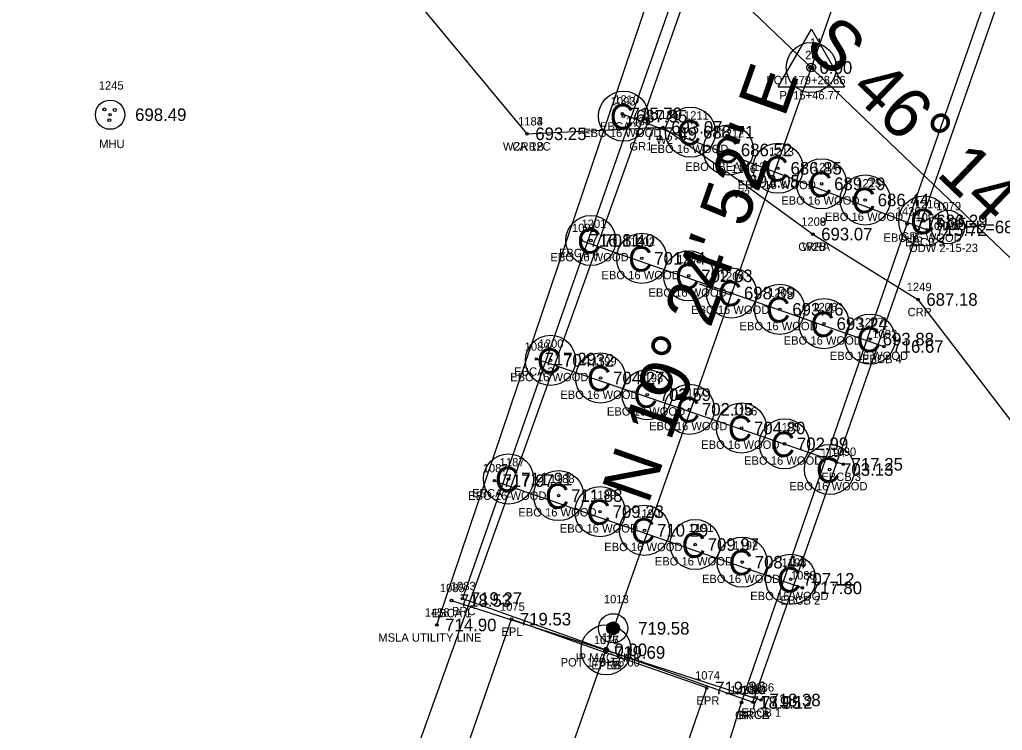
# Model space of a CAD drawing. Extents: x 1736563 to 1738032, y 1150548 to 1154248.
# Drawn here: x 1737322 to 1737439.5, y 1152598.1 to 1152683.1 of the extents above; entities that cross this region are included whole.
import ezdxf

# ---------------------------------------------------------------- set-up
doc = ezdxf.new("R2010")
doc.units = 0
for name, color, linetype in [('RD_EX_BldgApp', 7, 'Continuous'), ('RD_EX_Bridge', 7, 'Continuous'), ('RD_EX_Bridge_txCode', 7, 'Continuous'), ('RD_EX_DR_Inlet', 7, 'Continuous'), ('RD_EX_DV_Prop_txCode', 7, 'Continuous'), ('RD_EX_DV_PropPin', 7, 'Continuous'), ('RD_EX_GuardRail', 7, 'Continuous'), ('RD_EX_GuardRail_txCode', 7, 'Continuous'), ('RD_EX_H2O', 7, 'Continuous'), ('RD_EX_H2O_txCode', 7, 'Continuous'), ('RD_EX_Misc', 7, 'Continuous'), ('RD_EX_Misc_txCode', 7, 'Continuous'), ('RD_EX_Road', 7, 'Continuous'), ('RD_EX_Road_txCode', 7, 'Continuous'), ('RD_EX_TX_Bridge_ELEV', 7, 'Continuous'), ('RD_EX_TX_DV_Prop_ELEV', 7, 'Continuous'), ('RD_EX_TX_GuardRail_ELEV', 7, 'Continuous'), ('RD_EX_TX_H2O_ELEV', 7, 'Continuous'), ('RD_EX_TX_Misc_ELEV', 7, 'Continuous'), ('RD_EX_TX_Road_ELEV', 7, 'Continuous'), ('RD_EX_TX_UT_ELEV', 7, 'Continuous'), ('RD_EX_UT_txCode', 7, 'Continuous'), ('RD_HC_Cl', 7, 'Continuous'), ('RD_HC_Data', 7, 'Continuous'), ('RD_HC_Data_Tic', 7, 'Continuous'), ('RD_HC_Survey_ELEV', 7, 'Continuous'), ('RD_HC_txCode', 7, 'Continuous'), ('RD_SMD_Locator', 7, 'Continuous')]:
    doc.layers.add(name, color=color, linetype=linetype)

msp = doc.modelspace()

# ---------------------------------------------------------------- linework, layer by layer
at = {"layer": 'RD_EX_BldgApp'}
msp.add_lwpolyline([(1737382.66, 1152669.43), (1737398.93, 1152670.21), (1737408.18, 1152663.75), (1737416.87, 1152657.43)], dxfattribs=at)
at = {"layer": 'RD_EX_Bridge'}
for p, q in [((1737394.07, 1152671.82), (1737430.53, 1152657.96)), ((1737389.15, 1152656.68), (1737425.38, 1152643.99)), ((1737383.78, 1152642.49), (1737420.51, 1152629.9)), ((1737378.75, 1152627.93), (1737415.62, 1152615.11)), ((1737373.63, 1152613.6), (1737410.67, 1152601.69))]:
    msp.add_line(p, q, dxfattribs=at)
msp.add_lwpolyline([(1737409.7, 1152601.42), (1737459.22, 1152742.78), (1737424.43, 1152755.18), (1737374.94, 1152613.83), (1737409.7, 1152601.42)], dxfattribs=at)
for centre in [(1737394.21, 1152671.54), (1737402.23, 1152669.63), (1737406.76, 1152667.5), (1737412.7, 1152665.31), (1737417.92, 1152663.45), (1737423.13, 1152661.51), (1737430.14, 1152659.01), (1737390.3, 1152656.67), (1737396.4, 1152654.53), (1737402.02, 1152652.44), (1737407.13, 1152650.38), (1737412.91, 1152648.43), (1737418.21, 1152646.71), (1737423.73, 1152644.87), (1737385.48, 1152642.33), (1737391.47, 1152640.22), (1737397.05, 1152638.22), (1737402.1, 1152636.47), (1737408.33, 1152634.24), (1737413.47, 1152632.34), (1737418.87, 1152629.27), (1737380.46, 1152628.14), (1737386.45, 1152626.15), (1737391.41, 1152624.23), (1737396.73, 1152622), (1737402.79, 1152620.29), (1737408.42, 1152618.19), (1737414.21, 1152616.14)]:
    msp.add_circle(centre, 3, dxfattribs=at)
at = {"layer": 'RD_EX_DR_Inlet'}
for centre, radius in [((1737332.78, 1152671.72), 1.75), ((1737332.11, 1152672.35), 0.175), ((1737333.34, 1152672.28), 0.175), ((1737332.69, 1152671.06), 0.175)]:
    msp.add_circle(centre, radius, dxfattribs=at)
at = {"layer": 'RD_EX_DV_PropPin'}
for p, q in [((1737392.27, 1152609.97), (1737392.27, 1152610.56)), ((1737392.31, 1152609.9), (1737392.31, 1152610.64)), ((1737392.34, 1152609.84), (1737392.34, 1152610.69)), ((1737392.38, 1152609.79), (1737392.38, 1152610.74)), ((1737392.41, 1152609.75), (1737392.41, 1152610.78)), ((1737392.45, 1152609.72), (1737392.45, 1152610.82)), ((1737392.48, 1152609.68), (1737392.48, 1152610.85)), ((1737392.52, 1152609.66), (1737392.52, 1152610.88)), ((1737392.55, 1152609.63), (1737392.55, 1152610.9)), ((1737392.59, 1152609.61), (1737392.59, 1152610.92)), ((1737392.62, 1152609.59), (1737392.62, 1152610.94)), ((1737392.66, 1152609.57), (1737392.66, 1152610.96)), ((1737392.69, 1152609.56), (1737392.69, 1152610.97)), ((1737392.73, 1152609.55), (1737392.73, 1152610.99)), ((1737392.76, 1152609.54), (1737392.76, 1152611)), ((1737392.8, 1152609.53), (1737392.8, 1152611.01)), ((1737392.83, 1152609.52), (1737392.83, 1152611.02)), ((1737392.87, 1152609.51), (1737392.87, 1152611.02)), ((1737392.9, 1152609.51), (1737392.9, 1152611.02)), ((1737392.94, 1152609.51), (1737392.94, 1152611.03)), ((1737392.97, 1152609.51), (1737392.97, 1152611.03)), ((1737393.01, 1152609.51), (1737393.01, 1152611.03)), ((1737393.04, 1152609.51), (1737393.04, 1152611.02)), ((1737393.08, 1152609.51), (1737393.08, 1152611.02)), ((1737393.11, 1152609.52), (1737393.11, 1152611.02)), ((1737393.15, 1152609.53), (1737393.15, 1152611.01)), ((1737393.18, 1152609.54), (1737393.18, 1152611)), ((1737393.22, 1152609.55), (1737393.22, 1152610.99)), ((1737393.25, 1152609.56), (1737393.25, 1152610.97)), ((1737393.29, 1152609.57), (1737393.29, 1152610.96)), ((1737393.32, 1152609.59), (1737393.32, 1152610.94)), ((1737393.36, 1152609.61), (1737393.36, 1152610.92)), ((1737393.39, 1152609.63), (1737393.39, 1152610.9)), ((1737393.43, 1152609.66), (1737393.43, 1152610.88)), ((1737393.46, 1152609.68), (1737393.46, 1152610.85)), ((1737393.5, 1152609.72), (1737393.5, 1152610.82)), ((1737393.53, 1152609.75), (1737393.53, 1152610.78)), ((1737393.57, 1152609.79), (1737393.57, 1152610.74)), ((1737393.6, 1152609.84), (1737393.6, 1152610.69)), ((1737393.64, 1152609.9), (1737393.64, 1152610.64)), ((1737393.67, 1152609.97), (1737393.67, 1152610.56)), ((1737392.24, 1152610.07), (1737392.24, 1152610.46)), ((1737393.71, 1152610.07), (1737393.71, 1152610.46))]:
    msp.add_line(p, q, dxfattribs=at)
for radius in [1.75, 0.761]:
    msp.add_circle((1737392.97, 1152610.27), radius, dxfattribs=at)
at = {"layer": 'RD_EX_GuardRail'}
for points in [[(1737338.24, 1152511.65), (1737369.14, 1152594.73), (1737395.87, 1152669.44), (1737425.76, 1152754.51), (1737455.78, 1152858.18)], [(1737351.87, 1152429.26), (1737391.13, 1152545.98), (1737408.34, 1152601.39), (1737428.16, 1152658.66), (1737456.13, 1152738.69), (1737462.06, 1152749.07), (1737464.76, 1152758.57), (1737497.67, 1152845.09)]]:
    msp.add_lwpolyline(points, dxfattribs=at)
at = {"layer": 'RD_EX_H2O'}
for points in [[(1736941.84, 1152927.33), (1737042.79, 1152891.61), (1737121.65, 1152865.9), (1737201.8, 1152833.83), (1737271.75, 1152787.96), (1737327.38, 1152737.27), (1737368.53, 1152686.45), (1737382.66, 1152669.43)], [(1737416.87, 1152657.43), (1737429.45, 1152649.61), (1737450.39, 1152622.3), (1737469.7, 1152595.53), (1737481.35, 1152535.91), (1737513.9, 1152523.3), (1737579.93, 1152459.05), (1737654.23, 1152384.64), (1737738.06, 1152318.16), (1737784.96, 1152282.34)]]:
    msp.add_lwpolyline(points, dxfattribs=at)
for radius in [2, 0.15]:
    msp.add_circle((1737433.02, 1152658.28), radius, dxfattribs=at)
at = {"layer": 'RD_EX_Misc'}
msp.add_line((1737371.88, 1152610.67), (1737424.27, 1152765.64), dxfattribs=at)
at = {"layer": 'RD_EX_Road'}
for points in [[(1736868.01, 1151157.6), (1736882.54, 1151196.52), (1736892.4, 1151226.58), (1736911.77, 1151279.81), (1736926.32, 1151321.94), (1736959.92, 1151418.27), (1736977.6, 1151467.57), (1736993.86, 1151514.24), (1737026.63, 1151607.21), (1737059.17, 1151698.64), (1737091.53, 1151790.84), (1737119.9, 1151870.3), (1737125.51, 1151887.21), (1737129.74, 1151897.31), (1737157.61, 1151979.19), (1737191.07, 1152073.18), (1737224.57, 1152167.62), (1737258.08, 1152262.33), (1737292.51, 1152359.5), (1737326.83, 1152457.35), (1737361.84, 1152556.63), (1737380.81, 1152611.37), (1737392.07, 1152607.38)], [(1737114.69, 1151782.27), (1737149.29, 1151879.88), (1737171.36, 1151942.06), (1737180.55, 1151968.4), (1737214.61, 1152064.48), (1737248.04, 1152159.34), (1737281.83, 1152253.71), (1737315.68, 1152350.56), (1737350.18, 1152448.39), (1737384.95, 1152547.7), (1737404.17, 1152603.14), (1737392.07, 1152607.38)]]:
    msp.add_lwpolyline(points, dxfattribs=at)
at = {"layer": 'RD_HC_Cl'}
for p, q in [((1736879.96, 1151154.46), (1737935.1, 1154148.31)), ((1737384.75, 1152707.94), (1737485.65, 1152611.3))]:
    msp.add_line(p, q, dxfattribs=at)
at = {"layer": 'RD_HC_Data'}
for p, q in [((1737412.71, 1152675.06), (1737416.69, 1152681.94)), ((1737416.69, 1152681.94), (1737420.65, 1152675.06)), ((1737412.71, 1152675.06), (1737420.65, 1152675.06))]:
    msp.add_line(p, q, dxfattribs=at)
for centre, radius in [((1737416.68, 1152677.36), 3), ((1737416.68, 1152677.36), 0.529), ((1737416.68, 1152677.36), 0.282), ((1737392.13, 1152607.7), 3), ((1737392.13, 1152607.7), 0.282)]:
    msp.add_circle(centre, radius, dxfattribs=at)
at = {"layer": 'RD_HC_Data_Tic'}
msp.add_line((1737407.09, 1152650.13), (1737403.32, 1152651.46), dxfattribs=at)
at = {"layer": 'RD_SMD_Locator'}
for centre in [(1737416.68, 1152677.36), (1737416.68, 1152677.36), (1737332.78, 1152671.72), (1737394.07, 1152671.82), (1737394.21, 1152671.54), (1737382.66, 1152669.43), (1737382.66, 1152669.43), (1737395.87, 1152669.44), (1737398.93, 1152670.21), (1737402.23, 1152669.63), (1737406.76, 1152667.5), (1737412.7, 1152665.31), (1737408.18, 1152663.75), (1737417.92, 1152663.45), (1737423.13, 1152661.51), (1737428.16, 1152658.66), (1737430.14, 1152659.01), (1737430.53, 1152657.96), (1737389.15, 1152656.68), (1737390.3, 1152656.67), (1737416.87, 1152657.43), (1737416.87, 1152657.43), (1737396.4, 1152654.53), (1737402.02, 1152652.44), (1737407.13, 1152650.38), (1737429.45, 1152649.61), (1737412.91, 1152648.43), (1737418.21, 1152646.71), (1737423.73, 1152644.87), (1737425.38, 1152643.99), (1737383.78, 1152642.49), (1737385.48, 1152642.33), (1737391.47, 1152640.22), (1737397.05, 1152638.22), (1737402.1, 1152636.47), (1737408.33, 1152634.24), (1737413.47, 1152632.34), (1737418.87, 1152629.27), (1737420.51, 1152629.9), (1737380.46, 1152628.14), (1737378.75, 1152627.93), (1737386.45, 1152626.15), (1737391.41, 1152624.23), (1737396.73, 1152622), (1737402.79, 1152620.29), (1737408.42, 1152618.19), (1737414.21, 1152616.14), (1737415.62, 1152615.11), (1737373.63, 1152613.6), (1737374.94, 1152613.83), (1737371.88, 1152610.67), (1737380.81, 1152611.37), (1737392.97, 1152610.27), (1737392.07, 1152607.38), (1737392.07, 1152607.38), (1737392.13, 1152607.7), (1737404.17, 1152603.14), (1737408.34, 1152601.39), (1737409.7, 1152601.42), (1737409.7, 1152601.42), (1737410.67, 1152601.69)]:
    msp.add_circle(centre, 0.15, dxfattribs=at)

# ---------------------------------------------------------------- texts
at = {"layer": 'RD_EX_Bridge'}
for p in [(1737392.58, 1152669.98), (1737400.6, 1152668.07), (1737405.13, 1152665.94), (1737411.07, 1152663.74), (1737416.29, 1152661.89), (1737421.5, 1152659.95), (1737428.51, 1152657.45), (1737388.67, 1152655.11), (1737394.77, 1152652.96), (1737400.39, 1152650.88), (1737405.49, 1152648.82), (1737411.28, 1152646.87), (1737416.58, 1152645.14), (1737422.1, 1152643.31), (1737383.85, 1152640.77), (1737389.84, 1152638.65), (1737395.42, 1152636.66), (1737400.47, 1152634.91), (1737406.7, 1152632.67), (1737411.84, 1152630.78), (1737417.24, 1152627.71), (1737378.83, 1152626.58), (1737384.82, 1152624.59), (1737389.78, 1152622.67), (1737395.1, 1152620.44), (1737401.16, 1152618.73), (1737406.79, 1152616.63), (1737412.58, 1152614.57)]:
    msp.add_text('C', height=3, dxfattribs=at).set_placement(p)
at = {"layer": 'RD_EX_Bridge_txCode'}
for s, p in [('1210', (1737393.11, 1152673.04)), ('1093', (1737392.68, 1152672.82)), ('1211', (1737401.45, 1152671.13)), ('EBCA 5', (1737391.41, 1152669.82)), ('EBO 16 WOOD', (1737389.38, 1152669.04)), ('1212', (1737405.7, 1152669)), ('EBO 16 WOOD', (1737397.4, 1152667.13)), ('1213', (1737411.63, 1152666.81)), ('EBO I BEAM 12', (1737401.61, 1152665)), ('1214', (1737416.86, 1152664.95)), ('EBO 16 WOOD', (1737407.87, 1152662.81)), ('1215', (1737422.07, 1152663.01)), ('EBO 16 WOOD', (1737413.09, 1152660.95)), ('1216', (1737429.06, 1152660.51)), ('EBO 16 WOOD', (1737418.31, 1152659.01)), ('1094', (1737429.14, 1152658.96)), ('1201', (1737389.19, 1152658.17)), ('1091', (1737388.05, 1152657.68)), ('1202', (1737395.02, 1152656.03)), ('EBO 16 WOOD', (1737425.32, 1152656.51)), ('EBCB 5', (1737427.9, 1152655.96)), ('EBCA 4', (1737386.49, 1152654.68)), ('EBO 16 WOOD', (1737385.47, 1152654.17)), ('1203', (1737400.64, 1152653.94)), ('EBO 16 WOOD', (1737391.58, 1152652.03)), ('1204', (1737405.74, 1152651.88)), ('EBO 16 WOOD', (1737397.2, 1152649.94)), ('1205', (1737411.53, 1152649.93)), ('EBO 16 WOOD', (1737402.3, 1152647.88)), ('1206', (1737416.8, 1152648.21)), ('1207', (1737422.34, 1152646.37)), ('EBO 16 WOOD', (1737408.09, 1152645.93)), ('1092', (1737423.99, 1152644.99)), ('1200', (1737384.06, 1152643.83)), ('EBO 16 WOOD', (1737413.38, 1152644.21)), ('1089', (1737382.39, 1152643.49)), ('1199', (1737390.41, 1152641.72)), ('EBO 16 WOOD', (1737418.9, 1152642.37)), ('EBCB 4', (1737422.76, 1152641.99)), ('EBCA 3', (1737381.13, 1152640.49)), ('EBO 16 WOOD', (1737380.66, 1152639.83)), ('1198', (1737395.99, 1152639.72)), ('1197', (1737401.04, 1152637.97)), ('EBO 16 WOOD', (1737386.65, 1152637.72)), ('EBO 16 WOOD', (1737392.23, 1152635.72)), ('1196', (1737407.25, 1152635.74)), ('EBO 16 WOOD', (1737397.28, 1152633.97)), ('1195', (1737412.4, 1152633.84)), ('EBO 16 WOOD', (1737403.51, 1152631.74)), ('1194', (1737417.81, 1152630.77)), ('1090', (1737419.08, 1152630.9)), ('1187', (1737379.4, 1152629.64)), ('EBO 16 WOOD', (1737408.64, 1152629.84)), ('1087', (1737377.37, 1152628.93)), ('1188', (1737385.39, 1152627.65)), ('EBCB 3', (1737417.88, 1152627.9)), ('EBO 16 WOOD', (1737414.05, 1152626.77)), ('EBO 16 WOOD', (1737375.63, 1152625.64)), ('EBCA 2', (1737376.1, 1152625.93)), ('1189', (1737390.35, 1152625.73)), ('EBO 16 WOOD', (1737381.63, 1152623.65)), ('1190', (1737395.63, 1152623.5)), ('EBO 16 WOOD', (1737386.59, 1152621.73)), ('1191', (1737402.01, 1152621.79)), ('EBO 16 WOOD', (1737391.91, 1152619.5)), ('1192', (1737407.36, 1152619.69)), ('EBO 16 WOOD', (1737397.96, 1152617.79)), ('1193', (1737413.14, 1152617.64)), ('EBO 16 WOOD', (1737403.6, 1152615.69)), ('1088', (1737414.24, 1152616.11)), ('1085', (1737372.24, 1152614.6)), ('1083', (1737373.56, 1152614.83)), ('EBO 16 WOOD', (1737409.38, 1152613.64)), ('EBCB 2', (1737413, 1152613.11)), ('EBCA 1', (1737371.26, 1152611.6)), ('BRC', (1737373.69, 1152611.83)), ('1086', (1737409.26, 1152602.69)), ('1080', (1737408.28, 1152602.42)), ('1084', (1737408.32, 1152602.42)), ('BRCA', (1737407.96, 1152599.42)), ('BRCB', (1737407.98, 1152599.42)), ('EBCB 1', (1737408.33, 1152599.69))]:
    msp.add_text(s, height=1, dxfattribs=at).set_placement(p)
at = {"layer": 'RD_EX_DV_Prop_txCode'}
for s, p in [('1013', (1737391.87, 1152613.27)), ('IP MAG NAIL', (1737388.48, 1152606.27))]:
    msp.add_text(s, height=1, dxfattribs=at).set_placement(p)
at = {"layer": 'RD_EX_GuardRail_txCode'}
for s, p in [('1439', (1737394.52, 1152670.44)), ('GR1', (1737394.92, 1152667.44)), ('1436', (1737426.79, 1152659.66)), ('GR', (1737427.38, 1152656.66)), ('1435', (1737407, 1152602.39)), ('GR', (1737407.56, 1152599.39))]:
    msp.add_text(s, height=1, dxfattribs=at).set_placement(p)
at = {"layer": 'RD_EX_H2O'}
msp.add_text('ODW', height=1, dxfattribs=at).set_placement((1737431.35, 1152657.9))
at = {"layer": 'RD_EX_H2O_txCode'}
for s, p in [('1184', (1737381.6, 1152670.43)), ('CRRB', (1737380.93, 1152667.43)), ('1079', (1737431.63, 1152660.28)), ('1209', (1737415.48, 1152658.43)), ('CRRA', (1737415.13, 1152655.43)), ('ODW 2-15-23', (1737428.37, 1152655.28)), ('1249', (1737428.1, 1152650.61)), ('CRR', (1737428.2, 1152647.61))]:
    msp.add_text(s, height=1, dxfattribs=at).set_placement(p)
at = {"layer": 'RD_EX_Misc_txCode'}
for s, p in [('1185', (1737397.87, 1152671.21)), ('1183', (1737381.6, 1152670.43)), ('W2A 12C', (1737379.78, 1152667.43)), ('W2', (1737398.11, 1152668.21)), ('1186', (1737407.1, 1152664.75)), ('W2', (1737407.36, 1152661.75)), ('1208', (1737415.48, 1152658.43)), ('W2B', (1737415.58, 1152655.43)), ('1458', (1737370.44, 1152611.67)), ('MSLA UTILITY LINE', (1737364.88, 1152608.67))]:
    msp.add_text(s, height=1, dxfattribs=at).set_placement(p)
at = {"layer": 'RD_EX_Road_txCode'}
for s, p in [('1075', (1737379.43, 1152612.37)), ('EPL', (1737379.61, 1152609.37)), ('1076', (1737390.66, 1152608.38)), ('1077', (1737390.68, 1152608.38)), ('EPRB', (1737390.37, 1152605.38)), ('EPLB', (1737390.39, 1152605.38)), ('1074', (1737402.78, 1152604.14)), ('EPR', (1737402.94, 1152601.14))]:
    msp.add_text(s, height=1, dxfattribs=at).set_placement(p)
at = {"layer": 'RD_EX_TX_Bridge_ELEV'}
for s, p in [('715.70', (1737395.07, 1152671.07)), ('687.95', (1737395.71, 1152670.79)), ('688.71', (1737403.73, 1152668.88)), ('686.52', (1737408.26, 1152666.75)), ('686.85', (1737414.2, 1152664.56)), ('689.29', (1737419.42, 1152662.7)), ('686.44', (1737424.63, 1152660.76)), ('686.29', (1737431.64, 1152658.26)), ('715.72', (1737431.53, 1152657.21)), ('716.81', (1737390.15, 1152655.93)), ('701.40', (1737391.8, 1152655.92)), ('701.24', (1737397.9, 1152653.78)), ('702.63', (1737403.52, 1152651.69)), ('698.89', (1737408.63, 1152649.63)), ('693.46', (1737414.41, 1152647.68)), ('693.24', (1737419.71, 1152645.96)), ('693.88', (1737425.23, 1152644.12)), ('716.67', (1737426.38, 1152643.24)), ('717.29', (1737384.78, 1152641.74)), ('704.32', (1737386.98, 1152641.58)), ('704.27', (1737392.97, 1152639.47)), ('703.59', (1737398.55, 1152637.47)), ('702.05', (1737403.6, 1152635.72)), ('704.80', (1737409.83, 1152633.49)), ('702.99', (1737414.97, 1152631.59)), ('717.25', (1737421.51, 1152629.15)), ('703.13', (1737420.37, 1152628.52)), ('717.97', (1737379.75, 1152627.18)), ('711.91', (1737381.96, 1152627.39)), ('711.88', (1737387.95, 1152625.4)), ('709.23', (1737392.91, 1152623.48)), ('710.29', (1737398.23, 1152621.25)), ('709.97', (1737404.29, 1152619.54)), ('708.44', (1737409.92, 1152617.44)), ('707.12', (1737415.71, 1152615.39)), ('717.80', (1737416.62, 1152614.36)), ('718.53', (1737374.63, 1152612.85)), ('719.27', (1737375.94, 1152613.08)), ('718.38', (1737411.67, 1152600.94)), ('719.12', (1737410.7, 1152600.67)), ('719.12', (1737410.7, 1152600.67))]:
    msp.add_text(s, height=1.5, dxfattribs=at).set_placement(p)
at = {"layer": 'RD_EX_TX_DV_Prop_ELEV'}
msp.add_text('719.58', height=1.5, dxfattribs=at).set_placement((1737395.97, 1152609.52))
at = {"layer": 'RD_EX_TX_GuardRail_ELEV'}
for s, p in [('717.49', (1737396.87, 1152668.69)), ('717.35', (1737429.16, 1152657.91)), ('718.95', (1737409.34, 1152600.64))]:
    msp.add_text(s, height=1.5, dxfattribs=at).set_placement(p)
at = {"layer": 'RD_EX_TX_H2O_ELEV'}
for s, p in [('693.25', (1737383.66, 1152668.68)), ('EL=681.966', (1737435.02, 1152657.53)), ('693.07', (1737417.87, 1152656.68)), ('687.18', (1737430.45, 1152648.86))]:
    msp.add_text(s, height=1.5, dxfattribs=at).set_placement(p)
at = {"layer": 'RD_EX_TX_Misc_ELEV'}
for s, p in [('693.07', (1737399.93, 1152669.46)), ('693.25', (1737383.66, 1152668.68)), ('693.05', (1737409.18, 1152663)), ('693.07', (1737417.87, 1152656.68)), ('714.90', (1737372.88, 1152609.92))]:
    msp.add_text(s, height=1.5, dxfattribs=at).set_placement(p)
at = {"layer": 'RD_EX_TX_Road_ELEV'}
for s, p in [('719.53', (1737381.81, 1152610.62)), ('719.69', (1737393.07, 1152606.63)), ('719.69', (1737393.07, 1152606.63)), ('719.36', (1737405.17, 1152602.39))]:
    msp.add_text(s, height=1.5, dxfattribs=at).set_placement(p)
at = {"layer": 'RD_EX_TX_UT_ELEV'}
msp.add_text('698.49', height=1.5, dxfattribs=at).set_placement((1737335.78, 1152670.97))
at = {"layer": 'RD_EX_UT_txCode'}
for s, p in [('1245', (1737331.43, 1152674.72)), ('MHU', (1737331.48, 1152667.72))]:
    msp.add_text(s, height=1, dxfattribs=at).set_placement(p)
at = {"layer": 'RD_HC_Data'}
for s, rotation, p in [('S 46%%d 14\' 05" E', 316.2346, (1737415.67, 1152679.71)), ('N 19%%d 24\' 52" E', 70.5857, (1737397.16, 1152624.96))]:
    msp.add_text(s, height=6, rotation=rotation, dxfattribs=at).set_placement(p)
at = {"layer": 'RD_HC_Survey_ELEV'}
for p in [(1737417.68, 1152676.61), (1737417.68, 1152676.61), (1737393.13, 1152606.95)]:
    msp.add_text('0.00', height=1.5, dxfattribs=at).set_placement(p)
at = {"layer": 'RD_HC_txCode'}
for s, p in [('11', (1737416.52, 1152679.84)), ('28', (1737415.95, 1152678.36)), ('POT 179+28.86', (1737411.3, 1152675.36)), ('PI 15+46.77', (1737412.88, 1152673.54)), ('10', (1737391.64, 1152608.7)), ('POT 178+55.00', (1737386.69, 1152605.7))]:
    msp.add_text(s, height=1, dxfattribs=at).set_placement(p)

doc.saveas('drawing.dxf')
